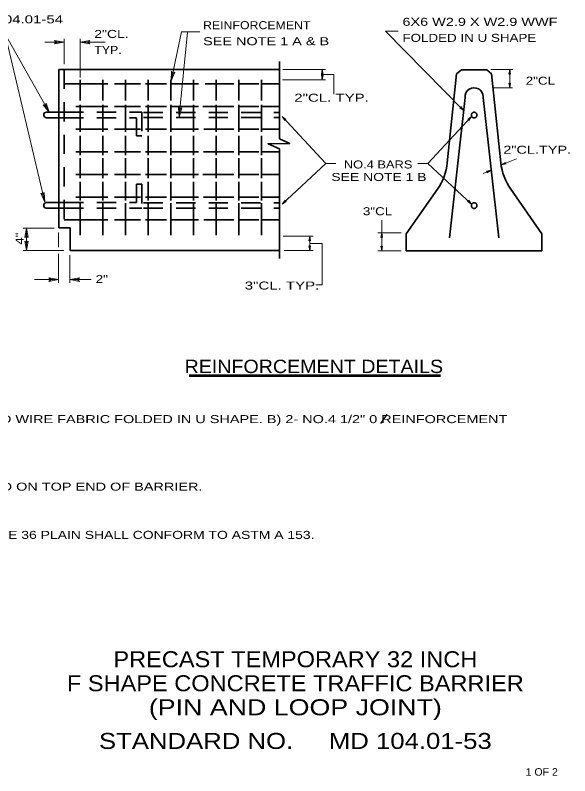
# Model space of a CAD drawing. Extents: x 12.4 to 19.4, y 5.8 to 15.9.
# Drawn here: x 15.25 to 19.4, y 5.84 to 11.54 of the extents above; entities that cross this region are included whole.
import ezdxf
from ezdxf.enums import TextEntityAlignment as Align

# ---------------------------------------------------------------- set-up
doc = ezdxf.new("R2010")
doc.units = 0
doc.header["$LTSCALE"] = 0.024
doc.linetypes.add('LONG_DASHED', pattern=[7.5, 6, -1.5])
for name, color, linetype, lineweight in [('1', 7, 'Continuous', 35), ('10', 7, 'Continuous', 13), ('12', 7, 'Continuous', 53), ('13', 7, 'Continuous', 25)]:
    doc.layers.add(name, color=color, linetype=linetype, lineweight=lineweight)

msp = doc.modelspace()

# ---------------------------------------------------------------- hatches: boundary and pattern name
at = {"layer": '10'}
for points in [[(15.545, 11.354), (15.6165, 11.3414), (15.545, 11.3288), (15.5585, 11.3414)], [(15.8089, 11.3288), (15.7374, 11.3414), (15.8089, 11.354), (15.7954, 11.3414)], [(16.446, 11.1178), (16.4189, 11.0505), (16.4214, 11.1231), (16.4309, 11.1072)], [(17.5435, 11.0998), (17.5498, 11.1356), (17.5561, 11.0998), (17.5498, 11.1066)], [(18.9484, 11.1007), (18.9547, 11.1364), (18.961, 11.1007), (18.9547, 11.1074)], [(17.5561, 11.0958), (17.5498, 11.06), (17.5435, 11.0958), (17.5498, 11.089)], [(18.961, 11.0352), (18.9547, 10.9995), (18.9484, 11.0352), (18.9547, 11.0285)], [(15.4809, 10.885), (15.5051, 10.8165), (15.459, 10.8726), (15.4766, 10.867)], [(16.4973, 10.8488), (16.4777, 10.7789), (16.4722, 10.8513), (16.4834, 10.8366)], [(18.5798, 10.8499), (18.6093, 10.8288), (18.5888, 10.8588), (18.589, 10.8495)], [(17.269, 10.7535), (17.2493, 10.784), (17.2783, 10.7621), (17.269, 10.7627)], [(18.6492, 10.754), (18.6689, 10.7845), (18.6399, 10.7626), (18.6492, 10.7632)], [(18.9276, 10.4294), (18.8922, 10.4218), (18.9229, 10.4411), (18.919, 10.4327)], [(18.78, 10.3743), (18.8154, 10.3819), (18.7847, 10.3626), (18.7886, 10.371)], [(15.4669, 10.2157), (15.471, 10.1432), (15.4423, 10.2099), (15.4577, 10.1997)], [(17.2711, 10.1567), (17.2493, 10.1277), (17.2798, 10.1475), (17.2705, 10.1475)], [(18.647, 10.1567), (18.6688, 10.1277), (18.6383, 10.1475), (18.6476, 10.1475)], [(15.3216, 9.8773), (15.3342, 9.9488), (15.3468, 9.8773), (15.3342, 9.8908)], [(17.45, 9.8534), (17.4563, 9.8891), (17.4626, 9.8534), (17.4563, 9.8601)], [(17.9893, 9.8767), (17.9956, 9.9124), (18.0019, 9.8767), (17.9956, 9.8834)], [(15.3468, 9.8516), (15.3342, 9.7801), (15.3216, 9.8516), (15.3342, 9.8381)], [(17.4626, 9.8158), (17.4563, 9.7801), (17.45, 9.8158), (17.4563, 9.8091)], [(18.0022, 9.814), (17.9959, 9.7783), (17.9896, 9.814), (17.9959, 9.8073)], [(15.5027, 9.5747), (15.5742, 9.5621), (15.5027, 9.5495), (15.5162, 9.5621)], [(15.7304, 9.5495), (15.6589, 9.5621), (15.7304, 9.5747), (15.7169, 9.5621)]]:
    msp.add_hatch(color=256, dxfattribs=at).paths.add_polyline_path(points)

# ---------------------------------------------------------------- linework, layer by layer
at = {"layer": '1'}
for p, q in [((17.2286, 11.1962), (17.2286, 10.6181)), ((15.5753, 11.1362), (15.5753, 9.9492)), ((17.2286, 11.1362), (15.5753, 11.1362)), ((18.5921, 11.135), (18.783, 11.135)), ((18.818, 11.1032), (18.783, 11.135)), ((15.7374, 11.0597), (15.7374, 10.9036)), ((15.9069, 11.0597), (15.9069, 10.9036)), ((16.0766, 11.0597), (16.0766, 10.9036)), ((16.2462, 11.0597), (16.2462, 10.9036)), ((16.4156, 11.0597), (16.4156, 10.9036)), ((16.5852, 11.0597), (16.5852, 10.9036)), ((16.7549, 11.0597), (16.7549, 10.9036)), ((16.9245, 11.0597), (16.9245, 10.9036)), ((17.0941, 11.0597), (17.0941, 10.9036)), ((18.888, 10.4383), (18.818, 11.1032)), ((15.6176, 11.0286), (15.9431, 11.0286)), ((15.9943, 11.0286), (16.1887, 11.0286)), ((16.2262, 11.0286), (16.383, 11.0286)), ((16.4138, 11.0286), (16.6218, 11.0286)), ((16.673, 11.0286), (16.8878, 11.0286)), ((16.9287, 11.0286), (17.0754, 11.0286)), ((17.2286, 11.0286), (17.0958, 11.0286)), ((18.6202, 10.926), (18.5025, 9.8759)), ((18.755, 10.926), (18.8728, 9.8759)), ((15.7032, 10.8591), (15.9431, 10.8591)), ((15.7374, 10.873), (15.7374, 10.6691)), ((15.9069, 10.873), (15.9069, 10.6691)), ((15.9943, 10.8591), (16.1887, 10.8591)), ((16.0766, 10.873), (16.0766, 10.6691)), ((16.2262, 10.8591), (16.383, 10.8591)), ((16.2462, 10.873), (16.2462, 10.6691)), ((16.4138, 10.8591), (16.6218, 10.8591)), ((16.4156, 10.873), (16.4156, 10.6691)), ((16.5852, 10.873), (16.5852, 10.6691)), ((16.6559, 10.8591), (16.8878, 10.8591)), ((16.7549, 10.873), (16.7549, 10.6691)), ((16.9245, 10.873), (16.9245, 10.6691)), ((16.9287, 10.8591), (17.0754, 10.8591)), ((17.0941, 10.873), (17.0941, 10.6691)), ((17.2286, 10.8591), (17.0958, 10.8591)), ((15.4832, 10.8178), (15.6176, 10.8178)), ((15.4832, 10.7754), (15.6176, 10.7754)), ((15.7032, 10.6895), (15.9431, 10.6895)), ((15.9943, 10.6895), (16.1887, 10.6895)), ((16.2262, 10.6895), (16.383, 10.6895)), ((16.4138, 10.6895), (16.6218, 10.6895)), ((16.6627, 10.6895), (16.8878, 10.6895)), ((16.9287, 10.6895), (17.0754, 10.6895)), ((17.2286, 10.6895), (17.0958, 10.6895)), ((15.7374, 10.6385), (15.7374, 10.4958)), ((15.9069, 10.6385), (15.9069, 10.4958)), ((16.0766, 10.6385), (16.0766, 10.4958)), ((16.2462, 10.6385), (16.2462, 10.4958)), ((16.4156, 10.6385), (16.4156, 10.4958)), ((16.5852, 10.6385), (16.5852, 10.4958)), ((16.7549, 10.6385), (16.7549, 10.4958)), ((16.9245, 10.6385), (16.9245, 10.4958)), ((17.0941, 10.6385), (17.0941, 10.4958)), ((17.2286, 9.7218), (17.2286, 10.5431)), ((15.7032, 10.52), (15.9431, 10.52)), ((15.9943, 10.52), (16.1887, 10.52)), ((16.2262, 10.52), (16.383, 10.52)), ((16.4138, 10.52), (16.6218, 10.52)), ((16.6593, 10.52), (16.8878, 10.52)), ((16.9287, 10.52), (17.0754, 10.52)), ((17.2286, 10.52), (17.0958, 10.52)), ((15.7374, 10.472), (15.7374, 10.3226)), ((15.9069, 10.472), (15.9069, 10.3226)), ((16.0766, 10.472), (16.0766, 10.3226)), ((16.2462, 10.472), (16.2462, 10.3226)), ((16.4156, 10.472), (16.4156, 10.3226)), ((16.5852, 10.472), (16.5852, 10.3226)), ((16.7549, 10.472), (16.7549, 10.3226)), ((16.9245, 10.472), (16.9245, 10.3226)), ((17.0941, 10.472), (17.0941, 10.3226)), ((15.7032, 10.3504), (15.9431, 10.3504)), ((15.9943, 10.3504), (16.1887, 10.3504)), ((16.2262, 10.3504), (16.383, 10.3504)), ((16.4138, 10.3504), (16.6218, 10.3504)), ((16.6559, 10.3504), (16.8878, 10.3504)), ((16.9287, 10.3504), (17.0754, 10.3504)), ((17.2286, 10.3504), (17.0958, 10.3504)), ((15.7374, 10.2953), (15.7374, 10.1561)), ((15.9069, 10.2953), (15.9069, 10.1561)), ((16.0766, 10.2953), (16.0766, 10.1561)), ((16.2462, 10.2953), (16.2462, 10.1561)), ((16.4156, 10.2953), (16.4156, 10.1561)), ((16.5852, 10.2953), (16.5852, 10.1561)), ((16.7549, 10.2953), (16.7549, 10.1561)), ((16.9245, 10.2953), (16.9245, 10.1561)), ((17.0941, 10.2953), (17.0941, 10.1561)), ((18.4128, 10.2397), (18.1789, 9.9056)), ((18.9624, 10.2397), (19.1964, 9.9056)), ((15.7032, 10.1808), (15.9431, 10.1808)), ((15.9943, 10.1808), (16.1887, 10.1808)), ((16.2262, 10.1808), (16.383, 10.1808)), ((16.4138, 10.1808), (16.6218, 10.1808)), ((16.6593, 10.1808), (16.8878, 10.1808)), ((16.9287, 10.1808), (17.0754, 10.1808)), ((17.2286, 10.1808), (17.0958, 10.1808)), ((15.482, 10.1395), (15.6176, 10.1395)), ((15.4826, 10.097), (15.6176, 10.097)), ((15.7374, 9.8961), (15.7374, 10.1357)), ((15.9069, 9.8961), (15.9069, 10.1357)), ((16.0766, 9.8961), (16.0766, 10.1357)), ((16.2462, 9.8961), (16.2462, 10.1357)), ((16.4156, 9.8961), (16.4156, 10.1357)), ((16.5852, 9.8961), (16.5852, 10.1357)), ((16.7549, 9.8961), (16.7549, 10.1357)), ((16.9245, 9.8961), (16.9245, 10.1357)), ((17.0941, 9.8961), (17.0941, 10.1357)), ((15.6176, 10.0112), (15.9431, 10.0112)), ((15.9943, 10.0112), (16.1887, 10.0112)), ((16.2262, 10.0112), (16.383, 10.0112)), ((16.4138, 10.0112), (16.6218, 10.0112)), ((16.6627, 10.0112), (16.8878, 10.0112)), ((16.9287, 10.0112), (17.0754, 10.0112)), ((17.2286, 10.0112), (17.0958, 10.0112)), ((18.1789, 9.7783), (18.1789, 9.9056)), ((19.1964, 9.7783), (19.1964, 9.9056)), ((17.2286, 9.7795), (15.6601, 9.7795)), ((18.1789, 9.7783), (19.1964, 9.7783))]:
    msp.add_line(p, q, dxfattribs=at)
at = {"layer": '1', "linetype": 'LONG_DASHED'}
for p, q in [((15.6176, 11.1362), (15.6176, 9.9492)), ((15.6176, 10.8178), (16.1975, 10.8178)), ((15.6176, 10.7754), (16.1579, 10.7754)), ((16.1579, 10.7754), (16.1579, 10.6386)), ((16.1975, 10.8178), (16.1975, 10.6386)), ((16.2113, 10.8153), (17.2286, 10.8153)), ((16.2113, 10.776), (17.2286, 10.776)), ((16.1579, 10.6386), (16.1975, 10.6386)), ((16.1579, 10.2764), (16.1579, 10.1395)), ((16.1579, 10.2764), (16.1975, 10.2764)), ((16.1975, 10.2764), (16.1975, 10.097)), ((15.6176, 10.1395), (16.1579, 10.1395)), ((15.6176, 10.097), (16.1975, 10.097)), ((16.2113, 10.1381), (17.2286, 10.1381)), ((16.2113, 10.0988), (17.2286, 10.0988))]:
    msp.add_line(p, q, dxfattribs=at)
at = {"layer": '1'}
for points in [[(18.4871, 10.4383), (18.557, 11.1032), (18.5921, 11.135)], [(15.6601, 9.7795), (15.6601, 9.9492), (15.5753, 9.9492)]]:
    msp.add_lwpolyline(points, dxfattribs=at)
for centre, radius, start, end in [((18.68761, 10.93187), 0.06769, 0, 184.94402), ((18.68761, 10.93187), 0.06769, 355.05598, 0), ((15.48468, 10.7966), 0.02122, 93.84029, 266.15971), ((18.06545, 10.48277), 0.42393, 325.00891, 353.98557), ((19.30964, 10.48276), 0.42393, 186.00677, 214.99444), ((15.48401, 10.11819), 0.02122, 93.84029, 266.15971)]:
    msp.add_arc(centre, radius, start, end, dxfattribs=at)
at = {"layer": '1', "linetype": 'LONG_DASHED'}
for centre, start, end in [((18.68816, 10.79542), 90.6627, 269.33729), ((18.68768, 10.79542), 270.64822, 89.35178), ((18.68816, 10.11704), 90.6627, 269.33729), ((18.68768, 10.11704), 270.64822, 89.35178)]:
    msp.add_arc(centre, 0.0212, start, end, dxfattribs=at)
at = {"layer": '10'}
for p, q in [((15.1742, 11.4026), (15.471, 10.1432)), ((16.4966, 11.418), (16.4189, 11.0505)), ((16.5416, 11.416), (16.4791, 10.788)), ((16.6322, 11.418), (16.4966, 11.418)), ((15.6165, 11.3414), (15.4715, 11.3414)), ((15.6165, 11.3414), (15.545, 11.354)), ((15.6165, 11.3414), (15.545, 11.3288)), ((15.6165, 11.1761), (15.6165, 11.3664)), ((15.7374, 11.0776), (15.7374, 11.3664)), ((15.7374, 11.3414), (15.8089, 11.354)), ((15.7374, 11.3414), (15.9244, 11.3414)), ((15.7374, 11.3414), (15.8089, 11.3288)), ((16.4189, 11.0505), (16.4214, 11.1231)), ((16.4189, 11.0505), (16.446, 11.1178)), ((17.2551, 11.1356), (17.5748, 11.1356)), ((17.5498, 11.1356), (17.5435, 11.0998)), ((17.5498, 11.06), (17.5498, 11.1356)), ((17.5498, 11.1356), (17.5561, 11.0998)), ((18.8124, 11.1364), (18.9777, 11.1364)), ((18.9547, 11.1364), (18.9484, 11.1007)), ((18.9547, 11.1364), (18.961, 11.1007)), ((18.9547, 10.9995), (18.9547, 11.1364)), ((17.2516, 11.06), (17.5748, 11.06)), ((17.5498, 11.06), (17.5435, 11.0958)), ((17.5498, 11.0981), (17.6362, 11.0981)), ((17.5498, 11.06), (17.5561, 11.0958)), ((17.6362, 11.0981), (17.6362, 10.9511)), ((18.8268, 10.9995), (18.9764, 10.9995)), ((18.9547, 10.9995), (18.9484, 11.0352)), ((18.9547, 10.9995), (18.961, 11.0352)), ((15.5051, 10.8165), (15.4809, 10.885)), ((15.5051, 10.8165), (15.459, 10.8726)), ((16.4777, 10.7789), (16.4722, 10.8513)), ((16.4777, 10.7789), (16.4973, 10.8488)), ((18.6093, 10.8288), (18.5888, 10.8588)), ((17.2493, 10.784), (17.269, 10.7535)), ((17.2493, 10.784), (17.2783, 10.7621)), ((18.6689, 10.7845), (18.6399, 10.7626)), ((18.6689, 10.7845), (18.6492, 10.754)), ((17.5767, 10.4323), (17.6515, 10.4323)), ((18.3414, 10.4323), (18.2666, 10.4323)), ((18.8922, 10.4218), (18.9229, 10.4411)), ((18.8922, 10.4218), (18.9276, 10.4294)), ((18.8923, 10.4218), (19.0063, 10.4677)), ((18.7547, 10.3566), (18.8085, 10.3789)), ((18.8154, 10.3819), (18.78, 10.3743)), ((18.8154, 10.3819), (18.7847, 10.3626)), ((15.471, 10.1432), (15.4423, 10.2099)), ((15.471, 10.1432), (15.4669, 10.2157)), ((17.2493, 10.1277), (17.2798, 10.1475)), ((18.6688, 10.1277), (18.6383, 10.1475)), ((18.6688, 10.1277), (18.647, 10.1567)), ((17.9958, 9.7791), (17.9958, 10.0076)), ((15.5403, 9.9488), (15.3092, 9.9488)), ((15.3342, 9.9488), (15.3216, 9.8773)), ((15.3342, 9.9488), (15.3342, 9.7801)), ((15.3342, 9.9488), (15.3468, 9.8773)), ((15.5742, 9.9142), (15.5742, 9.8051)), ((17.256, 9.8891), (17.4813, 9.8891)), ((17.4563, 9.8891), (17.45, 9.8534)), ((17.4563, 9.8891), (17.4563, 9.7801)), ((17.4563, 9.8891), (17.4626, 9.8534)), ((18.1401, 9.9131), (17.9673, 9.9131)), ((17.9956, 9.9124), (17.9893, 9.8767)), ((17.9956, 9.9124), (18.0019, 9.8767)), ((15.3342, 9.7801), (15.3216, 9.8516)), ((15.3342, 9.7801), (15.3468, 9.8516)), ((17.4563, 9.7801), (17.45, 9.8158)), ((17.4563, 9.8328), (17.5488, 9.8328)), ((17.4563, 9.7801), (17.4626, 9.8158)), ((17.9959, 9.7783), (17.9896, 9.814)), ((17.9959, 9.7783), (18.0022, 9.814)), ((15.613, 9.7801), (15.3092, 9.7801)), ((15.5742, 9.5371), (15.5742, 9.7551)), ((15.6589, 9.7445), (15.6589, 9.5371)), ((17.2657, 9.7801), (17.4813, 9.7801)), ((18.1401, 9.7791), (17.9673, 9.7791)), ((15.5742, 9.5621), (15.5027, 9.5747)), ((15.6589, 9.5621), (15.7304, 9.5747)), ((15.5742, 9.5621), (15.3929, 9.5621)), ((15.5742, 9.5621), (15.5027, 9.5495)), ((15.6589, 9.5621), (15.8177, 9.5621)), ((15.6589, 9.5621), (15.7304, 9.5495))]:
    msp.add_line(p, q, dxfattribs=at)
for points in [[(15.0476, 11.4026), (15.1742, 11.4026), (15.5051, 10.8165)], [(18.1199, 11.4238), (18.0245, 11.4238), (18.6093, 10.8288), (18.5798, 10.8499)], [(15.545, 11.354), (15.5585, 11.3414), (15.545, 11.3288)], [(15.8089, 11.3288), (15.7954, 11.3414), (15.8089, 11.354)], [(16.446, 11.1178), (16.4309, 11.1072), (16.4214, 11.1231)], [(17.5435, 11.0998), (17.5498, 11.1066), (17.5561, 11.0998)], [(17.5561, 11.0958), (17.5498, 11.089), (17.5435, 11.0958)], [(18.9484, 11.1007), (18.9547, 11.1074), (18.961, 11.1007)], [(18.961, 11.0352), (18.9547, 11.0285), (18.9484, 11.0352)], [(15.4809, 10.885), (15.4766, 10.867), (15.459, 10.8726)], [(16.4973, 10.8488), (16.4834, 10.8366), (16.4722, 10.8513)], [(18.5798, 10.8499), (18.589, 10.8495), (18.5888, 10.8588)], [(17.2492, 10.7845), (17.5767, 10.4323), (17.2493, 10.1277), (17.2711, 10.1567)], [(18.6689, 10.7845), (18.3414, 10.4323), (18.6688, 10.1277)], [(17.269, 10.7535), (17.269, 10.7627), (17.2783, 10.7621)], [(18.6492, 10.754), (18.6492, 10.7632), (18.6399, 10.7626)], [(18.9276, 10.4294), (18.919, 10.4327), (18.9229, 10.4411)], [(18.78, 10.3743), (18.7886, 10.371), (18.7847, 10.3626)], [(15.4669, 10.2157), (15.4577, 10.1997), (15.4423, 10.2099)], [(17.2711, 10.1567), (17.2705, 10.1475), (17.2798, 10.1475)], [(18.647, 10.1567), (18.6476, 10.1475), (18.6383, 10.1475)], [(15.3216, 9.8773), (15.3342, 9.8908), (15.3468, 9.8773)], [(17.45, 9.8534), (17.4563, 9.8601), (17.4626, 9.8534)], [(17.9893, 9.8767), (17.9956, 9.8834), (18.0019, 9.8767)], [(15.3468, 9.8516), (15.3342, 9.8381), (15.3216, 9.8516)], [(17.4626, 9.8158), (17.4563, 9.8091), (17.45, 9.8158)], [(17.5488, 9.8328), (17.5488, 9.5232), (17.5008, 9.5232)], [(18.0022, 9.814), (17.9959, 9.8073), (17.9896, 9.814)], [(15.5027, 9.5747), (15.5162, 9.5621), (15.5027, 9.5495)], [(15.7304, 9.5495), (15.7169, 9.5621), (15.7304, 9.5747)]]:
    msp.add_lwpolyline(points, dxfattribs=at)
for points in [[(15.545, 11.354), (15.6165, 11.3414), (15.545, 11.3288), (15.5585, 11.3414)], [(15.8089, 11.3288), (15.7374, 11.3414), (15.8089, 11.354), (15.7954, 11.3414)], [(16.446, 11.1178), (16.4189, 11.0505), (16.4214, 11.1231), (16.4309, 11.1072)], [(17.5435, 11.0998), (17.5498, 11.1356), (17.5561, 11.0998), (17.5498, 11.1066)], [(18.9484, 11.1007), (18.9547, 11.1364), (18.961, 11.1007), (18.9547, 11.1074)], [(17.5561, 11.0958), (17.5498, 11.06), (17.5435, 11.0958), (17.5498, 11.089)], [(18.961, 11.0352), (18.9547, 10.9995), (18.9484, 11.0352), (18.9547, 11.0285)], [(15.4809, 10.885), (15.5051, 10.8165), (15.459, 10.8726), (15.4766, 10.867)], [(16.4973, 10.8488), (16.4777, 10.7789), (16.4722, 10.8513), (16.4834, 10.8366)], [(18.5798, 10.8499), (18.6093, 10.8288), (18.5888, 10.8588), (18.589, 10.8495)], [(17.269, 10.7535), (17.2493, 10.784), (17.2783, 10.7621), (17.269, 10.7627)], [(18.6492, 10.754), (18.6689, 10.7845), (18.6399, 10.7626), (18.6492, 10.7632)], [(18.9276, 10.4294), (18.8922, 10.4218), (18.9229, 10.4411), (18.919, 10.4327)], [(18.78, 10.3743), (18.8154, 10.3819), (18.7847, 10.3626), (18.7886, 10.371)], [(15.4669, 10.2157), (15.471, 10.1432), (15.4423, 10.2099), (15.4577, 10.1997)], [(17.2711, 10.1567), (17.2493, 10.1277), (17.2798, 10.1475), (17.2705, 10.1475)], [(18.647, 10.1567), (18.6688, 10.1277), (18.6383, 10.1475), (18.6476, 10.1475)], [(15.3216, 9.8773), (15.3342, 9.9488), (15.3468, 9.8773), (15.3342, 9.8908)], [(17.45, 9.8534), (17.4563, 9.8891), (17.4626, 9.8534), (17.4563, 9.8601)], [(17.9893, 9.8767), (17.9956, 9.9124), (18.0019, 9.8767), (17.9956, 9.8834)], [(15.3468, 9.8516), (15.3342, 9.7801), (15.3216, 9.8516), (15.3342, 9.8381)], [(17.4626, 9.8158), (17.4563, 9.7801), (17.45, 9.8158), (17.4563, 9.8091)], [(18.0022, 9.814), (17.9959, 9.7783), (17.9896, 9.814), (17.9959, 9.8073)], [(15.5027, 9.5747), (15.5742, 9.5621), (15.5027, 9.5495), (15.5162, 9.5621)], [(15.7304, 9.5495), (15.6589, 9.5621), (15.7304, 9.5747), (15.7169, 9.5621)]]:
    msp.add_lwpolyline(points, close=True, dxfattribs=at)
at = {"layer": '10', "lineweight": 35}
msp.add_lwpolyline([(17.2286, 10.5431), (17.1446, 10.5799), (17.3063, 10.5812), (17.2286, 10.6181)], dxfattribs=at)
at = {"layer": '12'}
msp.add_line((16.5532, 8.8437), (18.435, 8.8437), dxfattribs=at)
at = {"layer": '13'}
msp.add_line((18.0336, 8.5526), (17.9854, 8.4845), dxfattribs=at)

# ---------------------------------------------------------------- texts
at = {"layer": '12'}
for s, width, p in [('SEE STD. MD 104.01-54', 1.4, (14.353, 11.4825)), ('6X6 W2.9 X W2.9 WWF ', 1.35, (18.1507, 11.4638)), ('REINFORCEMENT ', 1.15, (16.6569, 11.4387)), ('2"CL.', 1.3, (15.8422, 11.3732)), ('FOLDED IN U SHAPE', 1.25, (18.1507, 11.3438)), ('SEE NOTE 1 A & B', 1.35, (16.6569, 11.3187)), ('TYP.', 1.15, (15.8422, 11.2532)), ('2"CL', 1.25, (19.0746, 11.0227)), ('2"CL. TYP.', 1.4, (17.3405, 10.8951)), ('2"CL.TYP.', 1.35, (18.9065, 10.5055)), ('NO.4 BARS', 1.2, (17.7118, 10.3951)), ('SEE NOTE 1 B', 1.3, (17.6183, 10.3015)), ('3"CL', 1.25, (17.8547, 10.0447)), ('2"', 1.25, (15.8525, 9.537)), ('3"CL. TYP.', 1.4, (16.9696, 9.4879))]:
    msp.add_text(s, height=0.06, dxfattribs=dict(at, width=width)).set_placement(p)
at = {"layer": '12', "width": 1.25}
msp.add_text('4"', height=0.06, rotation=90, dxfattribs=at).set_placement((15.3128, 9.8235))
at = {"layer": '12', "width": 1.1}
msp.add_text('REINFORCEMENT DETAILS', height=0.1, dxfattribs=at).set_placement((17.4869, 8.8623), align=Align.CENTER)
at = {"layer": '13'}
for s, height, width, p in [('1. REINFORCEMENT: A) 6x6 W2.9 X W2.9 WELDED WIRE FABRIC FOLDED IN U SHAPE. B) 2- NO.4 1/2" 0 REINFORCEMENT', 0.06, 1.35, (12.621, 8.4872)), ('4. ALL BARRIERS SHALL HAVE  "T350" IMPRINTED ON TOP END OF BARRIER.', 0.06, 1.35, (12.621, 7.9812)), ('7. CONNECTOR LOOP -3/4" O ROD ASTM 709 GRADE 36 PLAIN SHALL CONFORM TO ASTM A 153.', 0.06, 1.3, (12.621, 7.6198)), ('1 OF 2', 0.0562, 1.05, (19.0739, 5.8457))]:
    msp.add_text(s, height=height, dxfattribs=dict(at, width=width)).set_placement(p)
for s, width, p in [('PRECAST TEMPORARY 32 INCH', 1.1, (17.3485, 6.6582)), ('F SHAPE CONCRETE TRAFFIC BARRIER', 1.1, (17.34845, 6.4782)), ('(PIN AND LOOP JOINT)', 1.25, (17.34845, 6.2982)), ('STANDARD NO.     MD 104.01-53', 1.2, (17.34855, 6.046))]:
    msp.add_text(s, height=0.12, dxfattribs=dict(at, width=width)).set_placement(p, align=Align.CENTER)

doc.saveas('drawing.dxf')
